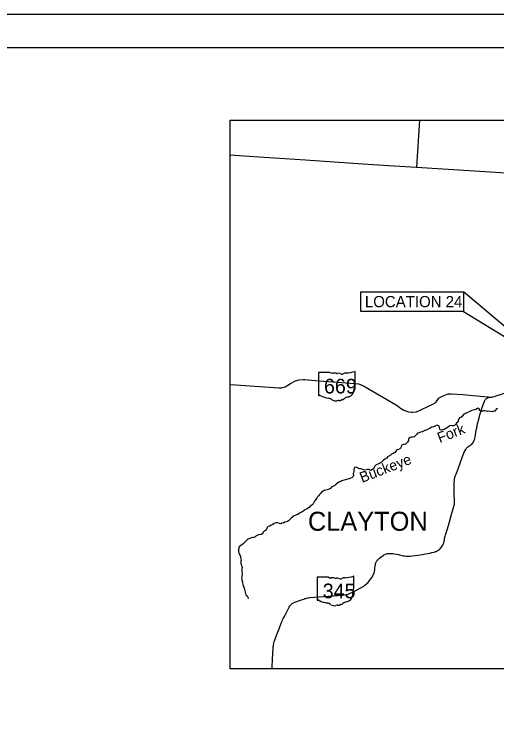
# Model space of a CAD drawing. Extents: x 0 to 34, y 0 to 22.
# Drawn here: x 7.94 to 15.25, y 11 to 22 of the extents above; entities that cross this region are included whole.
import ezdxf

# ---------------------------------------------------------------- set-up
doc = ezdxf.new("R2010")
doc.units = 0
for name, color, linetype in [('BR_P_Gen_Text', 7, 'Continuous'), ('GM_X_County', 7, 'Continuous'), ('GM_X_Minor_River', 7, 'Continuous'), ('GM_X_Minor_River_Text', 7, 'Continuous'), ('GM_X_State_Route', 7, 'Continuous'), ('GM_X_State_Shield', 7, 'Continuous'), ('GM_X_Township', 7, 'Continuous'), ('GM_X_Township_Road', 7, 'Continuous'), ('GM_X_Township_Text', 7, 'Continuous'), ('SH_Border', 7, 'Continuous'), ('SH_Cut_Line', 7, 'Continuous'), ('SH_Text', 7, 'Continuous')]:
    doc.layers.add(name, color=color, linetype=linetype)

msp = doc.modelspace()

# ---------------------------------------------------------------- linework, layer by layer
at = {"layer": 'BR_P_Gen_Text'}
for points in [[(13.189, 17.798), (14.743, 17.798), (14.743, 17.498), (13.189, 17.498)], [(14.743, 17.798), (14.743, 17.498), (16.029, 16.715)]]:
    msp.add_lwpolyline(points, close=True, dxfattribs=at)
at = {"layer": 'GM_X_County'}
msp.add_lwpolyline([(14.079, 20.398), (14.031, 19.685), (15.791, 19.578)], dxfattribs=at)
at = {"layer": 'GM_X_Minor_River'}
for points in [[(15.262, 16.031), (15.245, 16.026), (15.237, 16.01), (15.22, 15.988), (15.198, 15.991), (15.177, 15.982), (15.154, 15.984), (15.133, 15.989), (15.109, 15.987), (15.092, 15.99), (15.068, 15.994), (15.048, 15.997), (15.031, 15.99), (15.011, 15.99), (14.988, 16.002), (14.989, 16.018), (14.974, 16.036), (14.957, 16.03), (14.932, 16.016), (14.914, 16.01), (14.891, 16.005), (14.873, 15.998), (14.851, 15.989), (14.831, 15.979), (14.807, 15.969), (14.785, 15.962), (14.768, 15.952), (14.748, 15.942), (14.729, 15.921), (14.722, 15.904), (14.703, 15.892), (14.685, 15.891), (14.674, 15.872), (14.664, 15.85), (14.664, 15.83), (14.642, 15.816), (14.63, 15.793), (14.608, 15.773), (14.592, 15.767), (14.575, 15.767), (14.558, 15.771), (14.537, 15.767), (14.516, 15.75), (14.5, 15.74), (14.476, 15.725), (14.452, 15.712), (14.429, 15.706), (14.408, 15.702), (14.389, 15.709), (14.38, 15.727), (14.381, 15.748), (14.373, 15.769), (14.348, 15.78), (14.33, 15.773), (14.311, 15.764), (14.288, 15.755), (14.265, 15.746), (14.24, 15.732), (14.218, 15.721), (14.201, 15.712), (14.181, 15.704), (14.157, 15.697), (14.136, 15.686), (14.116, 15.678), (14.093, 15.671), (14.071, 15.662), (14.05, 15.656), (14.032, 15.634), (14.013, 15.614), (13.995, 15.603), (13.978, 15.597), (13.956, 15.595), (13.938, 15.592), (13.918, 15.578), (13.912, 15.561), (13.91, 15.544), (13.895, 15.522), (13.879, 15.507), (13.868, 15.49), (13.847, 15.485), (13.83, 15.487), (13.812, 15.475), (13.801, 15.455), (13.796, 15.435), (13.779, 15.419), (13.761, 15.409), (13.736, 15.402), (13.718, 15.384), (13.703, 15.362), (13.678, 15.348), (13.655, 15.336), (13.632, 15.318), (13.614, 15.308), (13.595, 15.297)], [(13.595, 15.297), (13.576, 15.274), (13.554, 15.262), (13.532, 15.249), (13.512, 15.227), (13.495, 15.214), (13.479, 15.202), (13.462, 15.194), (13.445, 15.185), (13.42, 15.175), (13.403, 15.158), (13.393, 15.137), (13.384, 15.119), (13.368, 15.11), (13.347, 15.092), (13.331, 15.096), (13.308, 15.104), (13.29, 15.107), (13.268, 15.099), (13.249, 15.096), (13.228, 15.103), (13.207, 15.113), (13.189, 15.115), (13.167, 15.117), (13.147, 15.128), (13.126, 15.135), (13.104, 15.139), (13.087, 15.126), (13.082, 15.101), (13.082, 15.076), (13.077, 15.057), (13.074, 15.039), (13.075, 15.017), (13.071, 14.998), (13.05, 14.982), (13.03, 14.975), (13.01, 14.966), (12.99, 14.957), (12.973, 14.952), (12.955, 14.95), (12.934, 14.945), (12.917, 14.94), (12.898, 14.932), (12.876, 14.919), (12.857, 14.913), (12.833, 14.899), (12.815, 14.882), (12.796, 14.865), (12.776, 14.853), (12.751, 14.841), (12.733, 14.824), (12.716, 14.814), (12.695, 14.804), (12.678, 14.797), (12.655, 14.792), (12.634, 14.786), (12.616, 14.776), (12.594, 14.762), (12.577, 14.744), (12.564, 14.725), (12.547, 14.707), (12.531, 14.69), (12.52, 14.673), (12.501, 14.646), (12.488, 14.625), (12.478, 14.607), (12.465, 14.587), (12.445, 14.566), (12.421, 14.548), (12.404, 14.532), (12.38, 14.515), (12.361, 14.507), (12.34, 14.495), (12.322, 14.481), (12.3, 14.465), (12.278, 14.454), (12.258, 14.442), (12.232, 14.425), (12.215, 14.417), (12.195, 14.408), (12.177, 14.402), (12.157, 14.389), (12.135, 14.376), (12.113, 14.347), (12.093, 14.328), (12.076, 14.319), (12.054, 14.312), (12.035, 14.307), (12.014, 14.292), (11.993, 14.298), (11.975, 14.285), (11.953, 14.287), (11.929, 14.298), (11.902, 14.296), (11.877, 14.29), (11.852, 14.271), (11.829, 14.261), (11.807, 14.248), (11.784, 14.244), (11.768, 14.226), (11.757, 14.203)], [(11.757, 14.203), (11.743, 14.183), (11.723, 14.171), (11.708, 14.155), (11.698, 14.133), (11.676, 14.12), (11.66, 14.119), (11.636, 14.115), (11.618, 14.106), (11.599, 14.095), (11.581, 14.082), (11.564, 14.076), (11.546, 14.074), (11.527, 14.07), (11.505, 14.059), (11.482, 14.048), (11.466, 14.039), (11.449, 14.025), (11.429, 14.004), (11.407, 13.979), (11.385, 13.965), (11.368, 13.952), (11.345, 13.933), (11.337, 13.917), (11.332, 13.896), (11.332, 13.878), (11.333, 13.859), (11.338, 13.839), (11.347, 13.821), (11.364, 13.79), (11.365, 13.772), (11.367, 13.754), (11.373, 13.734), (11.371, 13.715), (11.368, 13.695), (11.37, 13.679), (11.379, 13.655), (11.386, 13.638), (11.387, 13.619), (11.385, 13.599), (11.382, 13.575), (11.382, 13.55), (11.389, 13.531), (11.389, 13.515), (11.384, 13.49), (11.381, 13.465), (11.382, 13.445), (11.386, 13.428), (11.392, 13.406), (11.395, 13.383), (11.401, 13.364), (11.407, 13.346), (11.417, 13.325), (11.421, 13.306), (11.424, 13.287), (11.428, 13.27), (11.433, 13.249), (11.439, 13.226), (11.447, 13.205), (11.468, 13.189), (11.477, 13.169), (11.481, 13.148)]]:
    msp.add_lwpolyline(points, dxfattribs=at)
at = {"layer": 'GM_X_State_Route'}
msp.add_line((12.34, 16.468), (12.441, 16.46), dxfattribs=at)
for points in [[(11.205, 16.394), (11.287, 16.39), (11.803, 16.355), (11.946, 16.343), (11.982, 16.345), (12.039, 16.36), (12.121, 16.407), (12.197, 16.449), (12.253, 16.464), (12.315, 16.47), (12.34, 16.468)], [(12.441, 16.46), (12.56, 16.449), (12.963, 16.42), (13.099, 16.409), (13.152, 16.402), (13.196, 16.389), (13.223, 16.376), (13.252, 16.361), (13.712, 16.093), (13.739, 16.078), (13.789, 16.036), (13.842, 16.004), (13.913, 15.981), (13.956, 15.975), (13.973, 15.973), (14.031, 15.982), (14.108, 16.014), (14.281, 16.096), (14.313, 16.115), (14.337, 16.138), (14.365, 16.181), (14.38, 16.196), (14.396, 16.203), (14.449, 16.227), (14.497, 16.247), (14.514, 16.251), (14.558, 16.253), (14.734, 16.242), (15.102, 16.209), (15.117, 16.205), (15.137, 16.2)], [(15.137, 16.2), (15.15, 16.201), (15.162, 16.202), (15.173, 16.204), (15.188, 16.207), (15.213, 16.214), (15.241, 16.222), (15.273, 16.232), (15.321, 16.248), (15.348, 16.258), (15.436, 16.291), (15.484, 16.31), (15.532, 16.33), (15.577, 16.35), (15.672, 16.398)], [(15.024, 16.028), (15.038, 16.075), (15.048, 16.103), (15.056, 16.126), (15.061, 16.14), (15.067, 16.151), (15.075, 16.163), (15.084, 16.173), (15.094, 16.181), (15.104, 16.188), (15.113, 16.193), (15.123, 16.196), (15.137, 16.2)], [(11.843, 12.088), (11.843, 12.109), (11.85, 12.233), (11.861, 12.401), (11.861, 12.417), (11.864, 12.435), (11.865, 12.453), (11.867, 12.466), (11.87, 12.482), (11.874, 12.498), (11.878, 12.511), (11.914, 12.604), (11.95, 12.692), (11.982, 12.777), (11.994, 12.808), (12.002, 12.827), (12.011, 12.846), (12.02, 12.864), (12.044, 12.908), (12.082, 12.979), (12.101, 13.018), (12.11, 13.033), (12.118, 13.046), (12.125, 13.055), (12.135, 13.065), (12.147, 13.075), (12.158, 13.082), (12.178, 13.091), (12.201, 13.099), (12.241, 13.114), (12.291, 13.131), (12.325, 13.143), (12.344, 13.15), (12.355, 13.153), (12.367, 13.157), (12.383, 13.161), (12.395, 13.163), (12.417, 13.166), (12.488, 13.171), (12.618, 13.181), (12.7, 13.188), (12.747, 13.192), (12.773, 13.194), (12.801, 13.196), (12.841, 13.199), (12.877, 13.2), (12.896, 13.201), (12.917, 13.202), (12.94, 13.205), (12.963, 13.21), (12.995, 13.218), (13.018, 13.226), (13.039, 13.235), (13.056, 13.243), (13.079, 13.254), (13.223, 13.334), (13.233, 13.34), (13.25, 13.352), (13.276, 13.373), (13.294, 13.39), (13.311, 13.41), (13.337, 13.442), (13.358, 13.474), (13.377, 13.507), (13.382, 13.518), (13.382, 13.52), (13.389, 13.537), (13.394, 13.554), (13.398, 13.569), (13.401, 13.586), (13.403, 13.614), (13.407, 13.645), (13.41, 13.663), (13.413, 13.679), (13.418, 13.694), (13.421, 13.704), (13.425, 13.712), (13.429, 13.718), (13.434, 13.726), (13.438, 13.732), (13.444, 13.739), (13.451, 13.746), (13.459, 13.753), (13.469, 13.761), (13.494, 13.78), (13.529, 13.805), (13.539, 13.812), (13.551, 13.819), (13.563, 13.825), (13.576, 13.83), (13.591, 13.833), (13.603, 13.834), (13.621, 13.835), (13.637, 13.835), (13.654, 13.834), (13.675, 13.832), (13.701, 13.828), (13.757, 13.816), (13.811, 13.804), (13.813, 13.803), (13.833, 13.799), (13.856, 13.796), (13.88, 13.794), (13.91, 13.793), (13.936, 13.794), (13.972, 13.798), (14.092, 13.815), (14.168, 13.826), (14.205, 13.832), (14.233, 13.838), (14.267, 13.847), (14.298, 13.855), (14.319, 13.861), (14.333, 13.866), (14.348, 13.873), (14.362, 13.882), (14.374, 13.891), (14.389, 13.904), (14.402, 13.917), (14.412, 13.929), (14.422, 13.943), (14.431, 13.959), (14.437, 13.975), (14.445, 13.997), (14.45, 14.018), (14.455, 14.045), (14.459, 14.065), (14.466, 14.095), (14.472, 14.118), (14.476, 14.132), (14.486, 14.162), (14.496, 14.194), (14.516, 14.256), (14.57, 14.445), (14.585, 14.496), (14.594, 14.532), (14.603, 14.565), (14.606, 14.577), (14.608, 14.59), (14.61, 14.603), (14.611, 14.621), (14.605, 14.75), (14.603, 14.812), (14.603, 14.87), (14.603, 14.887), (14.605, 14.914), (14.607, 14.936), (14.61, 14.958), (14.616, 14.983), (14.625, 15.015), (14.633, 15.037), (14.667, 15.131), (14.719, 15.272), (14.746, 15.345), (14.761, 15.38), (14.768, 15.394), (14.778, 15.411), (14.787, 15.423), (14.797, 15.434), (14.811, 15.447), (14.826, 15.458), (14.847, 15.472), (14.862, 15.483), (14.876, 15.497), (14.886, 15.509), (14.895, 15.52), (14.902, 15.533), (14.908, 15.549), (14.915, 15.57), (14.919, 15.583), (14.925, 15.62), (14.939, 15.705), (14.945, 15.73), (14.959, 15.802), (14.965, 15.827), (14.972, 15.854), (14.98, 15.883), (14.99, 15.921), (15.003, 15.964), (15.013, 15.995), (15.024, 16.028)]]:
    msp.add_lwpolyline(points, dxfattribs=at)
at = {"layer": 'GM_X_State_Shield'}
for p, q in [((12.548, 16.571), (12.548, 16.234)), ((12.716, 16.577), (12.553, 16.577)), ((13.104, 16.409), (13.104, 16.586)), ((13.104, 16.409), (13.104, 16.409)), ((12.528, 13.469), (12.528, 13.131)), ((12.696, 13.475), (12.533, 13.475)), ((13.084, 13.306), (13.084, 13.483)), ((13.084, 13.307), (13.084, 13.306))]:
    msp.add_line(p, q, dxfattribs=at)
for centre, major_axis, start_param, end_param in [((12.554, 16.572), (0.00644, 0), 1.712693, 3.28349), ((12.755, 16.616), (0.0625, 0), 4.042523, 4.731795), ((12.776, 16.388), (0.224, 0), 1.404758, 1.657858), ((12.827, 16.574), (0.018, 0), 3.836095, 5.185415), ((12.853, 16.535), (0.0375, 0), 0.950623, 2.079405), ((12.901, 16.588), (0.0451, 0), 4.081561, 5.145723), ((12.981, 16.474), (0.119, 0), 1.699011, 2.107814), ((12.906, 17.038), (0.59, 0), 4.814394, 5.042369), ((13.098, 16.586), (0.00619, 0), 6.141152, 7.989035), ((13.103, 16.396), (0.00958, 0), 1.883978, 3.671073), ((13.042, 16.374), (0.0575, 0), 5.934695, 6.695948), ((13.097, 16.408), (0.00663, 0), 5.05454, 6.418171), ((12.939, 16.313), (0.148, 0), 5.101752, 6.440018), ((13.126, 16.335), (0.0418, 0), 2.387724, 3.262537), ((12.554, 16.233), (0.0065, 0), 3.00124, 4.508301), ((12.555, 16.268), (0.0496, 0), 4.665946, 4.897461), ((12.565, 16.214), (0.0179, 0), 0.519207, 1.627899), ((12.791, 16.518), (0.426, 0), 4.195997, 4.488961), ((12.664, 16.082), (0.133, 0), 0.823519, 1.323587), ((12.899, 16.201), (0.0477, 0), 4.937069, 5.64225), ((13.001, 16.139), (0.0808, 0), 1.647645, 2.488434), ((12.808, 16.213), (0.0846, 0), 4.026481, 4.996735), ((12.857, 16.096), (0.0695, 0), 1.495662, 1.94098), ((12.863, 16.187), (0.0451, 0), 4.691044, 5.507374), ((12.904, 16.155), (0.0127, 0), 1.147584, 2.315152), ((12.534, 13.47), (0.00644, 0), 1.712693, 3.28349), ((12.735, 13.514), (0.0625, 0), 4.042523, 4.731795), ((12.755, 13.285), (0.224, 0), 1.404758, 1.657858), ((12.806, 13.471), (0.018, 0), 3.836095, 5.185415), ((12.833, 13.432), (0.0375, 0), 0.950623, 2.079405), ((12.881, 13.486), (0.0451, 0), 4.081561, 5.145723), ((12.961, 13.372), (0.119, 0), 1.699011, 2.107814), ((12.886, 13.935), (0.59, 0), 4.814394, 5.042369), ((13.078, 13.484), (0.00619, 0), 6.141152, 7.989035), ((12.919, 13.21), (0.148, 0), 5.101752, 6.440018), ((13.106, 13.233), (0.0418, 0), 2.387724, 3.262537), ((13.082, 13.293), (0.00958, 0), 1.883978, 3.671073), ((13.021, 13.271), (0.0575, 0), 5.934695, 6.695948), ((13.077, 13.306), (0.00663, 0), 5.05454, 6.418171), ((12.534, 13.131), (0.0065, 0), 3.00124, 4.508301), ((12.535, 13.165), (0.0496, 0), 4.665946, 4.897461), ((12.545, 13.112), (0.0179, 0), 0.519207, 1.627899), ((12.771, 13.415), (0.426, 0), 4.195997, 4.488961), ((12.981, 13.036), (0.0808, 0), 1.647645, 2.488434), ((12.644, 12.98), (0.133, 0), 0.823519, 1.323587), ((12.788, 13.11), (0.0846, 0), 4.026481, 4.996735), ((12.837, 12.993), (0.0695, 0), 1.495662, 1.94098), ((12.843, 13.085), (0.0451, 0), 4.691044, 5.507374), ((12.884, 13.052), (0.0127, 0), 1.147584, 2.315152), ((12.879, 13.099), (0.0477, 0), 4.937069, 5.64225)]:
    msp.add_ellipse(centre, major_axis=major_axis, ratio=0.8, start_param=start_param, end_param=end_param, dxfattribs=at)
at = {"layer": 'GM_X_Township'}
msp.add_lwpolyline([(11.205, 19.875), (11.565, 19.85), (12.351, 19.798), (13.218, 19.738), (13.613, 19.712), (14.031, 19.685)], dxfattribs=at)
at = {"layer": 'GM_X_Township_Road'}
msp.add_line((12.34, 16.468), (12.441, 16.46), dxfattribs=at)
at = {"layer": 'SH_Border'}
msp.add_lwpolyline([(1.5, 21.5), (33.5, 21.5), (33.5, 0.5), (1.5, 0.5)], close=True, dxfattribs=at)
at = {"layer": 'SH_Cut_Line'}
msp.add_lwpolyline([(0, 0), (34, 0), (34, 22), (0, 22)], close=True, dxfattribs=at)
at = {"layer": 'SH_Text'}
msp.add_lwpolyline([(11.205, 20.398), (22.295, 20.398), (22.295, 12.088), (11.205, 12.088)], close=True, dxfattribs=at)

# ---------------------------------------------------------------- texts
at = {"layer": 'BR_P_Gen_Text'}
msp.add_text('LOCATION 24', height=0.17, dxfattribs=at).set_placement((13.25, 17.565))
at = {"layer": 'GM_X_Minor_River_Text'}
for s, p in [('Fork', (14.385, 15.505)), ('Buckeye', (13.207, 14.902))]:
    msp.add_text(s, height=0.1598, rotation=21.2322, dxfattribs=at).set_placement(p)
at = {"layer": 'GM_X_State_Shield'}
for s, p in [('669', (12.63, 16.258)), ('345', (12.611, 13.155))]:
    msp.add_text(s, height=0.2225, dxfattribs=at).set_placement(p)
at = {"layer": 'GM_X_Township_Text'}
msp.add_text('CLAYTON', height=0.2876, rotation=0, dxfattribs=at).set_placement((12.386, 14.178))

doc.saveas('drawing.dxf')
